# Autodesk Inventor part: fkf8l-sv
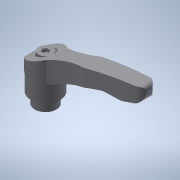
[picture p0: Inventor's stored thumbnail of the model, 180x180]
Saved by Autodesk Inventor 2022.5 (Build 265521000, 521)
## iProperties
Created: 2017-09
Part Number: fkf8l-sv
Material: 一般
Document SubType Name: Modeling
Designer: imaocorp
Density: 1 g/cm^3
Appearance: 既定
Author: imaocorp
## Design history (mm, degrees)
node "fkf8l-sv.x_t1"
node "fkf8l-sv"
node "Base1"
